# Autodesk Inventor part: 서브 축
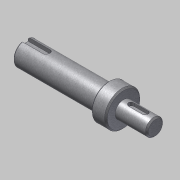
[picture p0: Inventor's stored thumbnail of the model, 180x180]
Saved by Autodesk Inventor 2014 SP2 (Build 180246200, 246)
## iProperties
Created: 2016-04
Part Number: 서브 축
Document SubType Name: Modeling
Designer: mdu
Density: 1 g/cm^3
Mass: 19.9624 g
Surface Area: 57.7178 cm^2
Volume: 19.9624 cm^3
Material: 강철, 연강
Appearance: 금속-강(스테인리스, 브러시됨)
Author: mdu
Revision Number: 1
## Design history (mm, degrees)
sketch "스케치1"
  geometry: L1 (-16.331, 0)-(-108.831, 0); L2 (-16.331, 0)-(-16.331, -6); L3 (-16.331, -6)-(-38.831, -6); L4 (-38.831, -12.5)-(-46.5, -12.5); L5 (-46.5, -8.5)-(-108.831, -8.5); L6 (-108.831, -8.5)-(-108.831, 0); L7 (-46.5, -8.5)-(-46.5, -12.5); L8 (-38.831, -6)-(-38.831, -12.5); L9 (-46.5, 12.249)-(-46.5, -12.249) reference; L10 (-38.831, -17)-(-38.831, 17) reference; 2 further points
  constraints: 17 end point, 4 perpendicular, 2 collinear, 2 parallel, 1 horizontal, 1 midpoint, 1 point on line
  dimensions: "d1" = 12 diameter of L3 L1; "d2" = 25 diameter of L4 L1; "d3" = 17 diameter of L5 L1; "d18" = 22.5 distance of L2.end L3.end; "d20" = 70 distance between parallel lines of L6 L8; "d21" = 7.66872 distance of L4.start L4.end (derived)
revolve "회전1" sketch "스케치1" stored, may be unused: angle "d5" = 90 deg
chamfer "모따기1" distance "d6" = 1; stored, may be unused: second distance "d7" = 2, angle "d8" = 45 deg
node "작업 평면1"
sketch "스케치2"
  geometry: L1 (11.25, 5)-(11.25, -5) reference; L2 (-5.75, -2)-(4.25, -2); L3 (4.25, 2)-(-5.75, 2); A1 r 2 centre (4.25, 0) between (4.25, -2) and (4.25, 2); A2 r 2 centre (-5.75, 0) between (-5.75, 2) and (-5.75, -2); 2 further points
  constraints: 4 end point, 4 point on circle, 4 tangent, 2 centre point, 1 horizontal alignment, 1 midpoint, 1 parallel, 1 perpendicular
  dimensions: "d9" = 4 distance between parallel lines of L2 L3; "d10" = 14 dimension on A1 A2; "d11" = 5 distance edge to line of A1 L1
extrude "돌출1" cut sketch "스케치2" distance "d12" = 2.5; taper "d13" = 0 deg
node "작업 평면2"
sketch "스케치3"
  geometry: L1 (-31.166, -7.5)-(-31.166, 7.5) reference; L2 (-31.166, 2.5)-(-15.666, 2.5); L3 (-15.666, -2.5)-(-31.166, -2.5); A1 r 2.5 centre (-15.666, 0) between (-15.666, -2.5) and (-15.666, 2.5); 2 further points
  constraints: 4 end point, 2 perpendicular, 2 point on circle, 2 point on line, 2 tangent, 1 centre point, 1 horizontal alignment, 1 midpoint
  dimensions: "d14" = 5 distance between parallel lines of L3 L2; "d15" = 18 dimension on A1 L1
extrude "돌출2" cut sketch "스케치3" distance "d16" = 3; taper "d17" = 0 deg
sketch "스케치4"
  geometry: C1 r 12.5 at (0, 0) reference; 1 further point
extrude "돌출3" join sketch "스케치4" distance "d22" = 3; taper "d23" = 0 deg
chamfer "모따기2" distance "d24" = 1; stored, may be unused: second distance "d25" = 2, angle "d26" = 45 deg
node "솔리드1"
node "참조4"
node "참조5"
